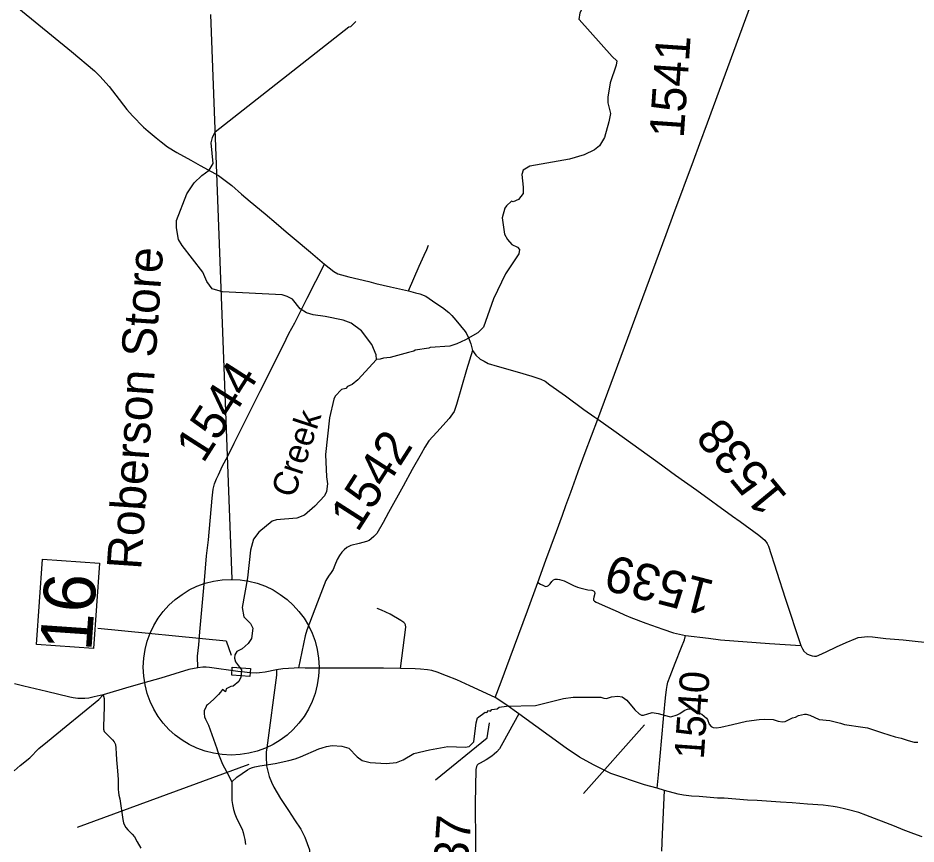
# Model space of a CAD drawing. Extents: x 2599057 to 2600057, y 728628 to 732947.
# Drawn here: x 2599143.3 to 2599259.1, y 731800 to 731906.7 of the extents above; entities that cross this region are included whole.
import ezdxf

# ---------------------------------------------------------------- set-up
doc = ezdxf.new("R2010")
doc.units = 0
for name, color, linetype in [('Old_Level_1', 7, 'Continuous'), ('Old_Level_29', 7, 'Continuous'), ('Old_Level_31', 7, 'Continuous'), ('Old_Level_32', 7, 'Continuous'), ('Old_Level_38', 7, 'Continuous'), ('Old_Level_50', 7, 'Continuous'), ('Old_Level_59', 7, 'Continuous')]:
    doc.layers.add(name, color=color, linetype=linetype)

msp = doc.modelspace()

# ---------------------------------------------------------------- linework, layer by layer
at = {"layer": 'Old_Level_1'}
msp.add_line((2599170.91, 731834.22), (2599168.16, 731907.13), dxfattribs=at)
msp.add_circle((2599170.77, 731822.87), 11.34, dxfattribs=at)
at = {"layer": 'Old_Level_29'}
msp.add_line((2599226.69, 731806.97), (2599225.71, 731807.27), dxfattribs=at)
for points in [[(2599166.45, 731822.8), (2599165.29, 731822.56), (2599161.7, 731821.47), (2599160.14, 731821.03), (2599157.58, 731820.28), (2599154.24, 731819.31)], [(2599172.1, 731822.26), (2599171.61, 731822.31), (2599167.99, 731822.85), (2599167.53, 731822.88), (2599167.11, 731822.86), (2599166.45, 731822.8)], [(2599176.63, 731822.53), (2599175.14, 731822.24), (2599174.44, 731822.14), (2599174.06, 731822.1), (2599173.22, 731822.13), (2599172.1, 731822.26)], [(2599179.44, 731822.78), (2599178.89, 731822.74), (2599177.45, 731822.65), (2599176.63, 731822.53)], [(2599192.63, 731822.7), (2599190.42, 731822.75), (2599183.31, 731822.75), (2599180.31, 731822.76), (2599179.44, 731822.78)], [(2599204.83, 731818.96), (2599201.57, 731820.46), (2599199.86, 731821.23), (2599198.54, 731821.78), (2599197.33, 731822.25), (2599196.67, 731822.44), (2599196.11, 731822.54), (2599195.2, 731822.63), (2599194.52, 731822.66), (2599192.63, 731822.7)], [(2599154.24, 731819.31), (2599153.1, 731819.05), (2599152.4, 731818.88), (2599151.89, 731818.83), (2599151.57, 731818.84), (2599150.99, 731818.84), (2599150.38, 731818.91), (2599149.94, 731818.99), (2599146.94, 731819.75), (2599144.04, 731820.42), (2599142.84, 731820.74)], [(2599207.89, 731816.84), (2599206.2, 731818.04), (2599204.83, 731818.96)], [(2599225.71, 731807.27), (2599224.08, 731807.69), (2599219.76, 731809.16), (2599218.98, 731809.53), (2599218.36, 731809.83), (2599217.5, 731810.27), (2599215.7, 731811.28), (2599213.99, 731812.43), (2599207.89, 731816.84)], [(2599259.9, 731800.97), (2599258.83, 731801.37), (2599257.45, 731801.88), (2599256.32, 731802.36), (2599252.64, 731803.79), (2599251.73, 731804.11), (2599250.22, 731804.51), (2599249.71, 731804.63), (2599248.93, 731804.8), (2599248.41, 731804.88), (2599247.13, 731805.07), (2599245.11, 731805.21), (2599243.13, 731805.36), (2599241.62, 731805.46), (2599238.63, 731805.68), (2599237.37, 731805.73), (2599234.38, 731805.96), (2599233.49, 731805.99), (2599231.15, 731806.2), (2599230.17, 731806.25), (2599229.14, 731806.36), (2599228.44, 731806.48), (2599226.69, 731806.97)]]:
    msp.add_lwpolyline(points, dxfattribs=at)
at = {"layer": 'Old_Level_31'}
for p, q in [((2599201.09, 731866.03), (2599201.09, 731866.03)), ((2599172.05, 731822.25), (2599172.05, 731822.25)), ((2599205.61, 731818.47), (2599205.61, 731818.47)), ((2599226.49, 731816.7), (2599226.49, 731816.7)), ((2599216.21, 731806.58), (2599224.09, 731815.45)), ((2599150.95, 731802.23), (2599173.1, 731810.35)), ((2599175.34, 731810.11), (2599175.34, 731810.11))]:
    msp.add_line(p, q, dxfattribs=at)
for points in [[(2599153.79, 731836.3), (2599153.03, 731825.31), (2599145.68, 731825.82), (2599146.44, 731836.81), (2599153.79, 731836.3)], [(2599153.58, 731827.92), (2599170.11, 731826.29), (2599170.77, 731824.44)], [(2599197.11, 731808.35), (2599203.79, 731813.77), (2599204.11, 731815.7)]]:
    msp.add_lwpolyline(points, dxfattribs=at)
at = {"layer": 'Old_Level_32'}
for points in [[(2599218.06, 731854.89), (2599221.94, 731865.36), (2599223.46, 731869.43), (2599224.29, 731871.74), (2599226.88, 731878.72), (2599227.87, 731881.42), (2599230.41, 731888.22), (2599231.23, 731890.45), (2599232.2, 731893.12), (2599237.18, 731906.61), (2599244.57, 731926.73), (2599247.08, 731933.51), (2599249.88, 731941.02), (2599250.89, 731943.93)], [(2599143.4, 731907.91), (2599150.19, 731902.36), (2599153.15, 731899.87), (2599153.84, 731899.17), (2599155.02, 731897.81), (2599155.89, 731896.69), (2599157.33, 731894.87), (2599158.06, 731894.02), (2599159.47, 731892.56), (2599160.05, 731892.07), (2599161.09, 731891.18), (2599161.73, 731890.68), (2599162.54, 731890.04), (2599163.75, 731889.31), (2599165.58, 731888.31), (2599166.77, 731887.63), (2599167.79, 731887.07), (2599169.12, 731886.33), (2599170.84, 731885.05), (2599172.12, 731883.95), (2599173.23, 731883), (2599175.16, 731881.39), (2599176.56, 731880.19), (2599177.86, 731879.05), (2599178.89, 731878.19), (2599180.99, 731876.44), (2599182.83, 731874.89)], [(2599193.63, 731871.44), (2599195.02, 731874.62), (2599195.68, 731876.06), (2599196, 731876.78), (2599196.24, 731877.35)], [(2599166.45, 731822.8), (2599166.42, 731824.3), (2599166.58, 731825.78), (2599166.72, 731827.46), (2599167.35, 731834.08), (2599167.6, 731837.25), (2599167.85, 731839.33), (2599168.32, 731844.69), (2599168.46, 731845.85), (2599168.61, 731846.53), (2599168.89, 731847.17), (2599169.12, 731847.69), (2599169.67, 731848.86), (2599170.35, 731850.13), (2599171.15, 731851.78), (2599174.51, 731858.5), (2599177.51, 731864.47), (2599178.21, 731865.93), (2599178.97, 731867.33), (2599180.57, 731870.52), (2599182.83, 731874.89)], [(2599182.83, 731874.89), (2599184.02, 731873.95), (2599184.52, 731873.66), (2599185.97, 731873.26), (2599188.55, 731872.64), (2599189.44, 731872.4), (2599191.34, 731871.98), (2599193.63, 731871.44)], [(2599193.63, 731871.44), (2599194.53, 731871.2), (2599195.1, 731871.05), (2599195.9, 731870.77), (2599197.17, 731869.86), (2599198.02, 731869.3), (2599198.83, 731868.66), (2599199.24, 731868.28), (2599199.75, 731867.65), (2599200.96, 731866.22), (2599201.05, 731866.06)], [(2599201.05, 731866.06), (2599201.34, 731865.53), (2599201.68, 731864.6), (2599201.91, 731863.74)], [(2599201.91, 731863.74), (2599201.14, 731861.24), (2599199.82, 731856.8), (2599199.52, 731855.87), (2599198.89, 731854.98), (2599197.29, 731853.23), (2599196.27, 731852.08), (2599195.75, 731851.28), (2599195.29, 731850.42), (2599194.13, 731848.39), (2599192.96, 731846.26), (2599191.08, 731842.86), (2599190.37, 731841.57), (2599189.56, 731840.14), (2599189.19, 731839.73), (2599188.85, 731839.43), (2599188.56, 731839.24), (2599188.24, 731839.08), (2599187.28, 731838.83), (2599186.21, 731838.57), (2599185.7, 731838.31), (2599185.34, 731838.02), (2599185.05, 731837.74), (2599184.73, 731837.31), (2599184.44, 731836.76), (2599184.14, 731836.04), (2599183.91, 731835.49), (2599183.66, 731835.08), (2599183.33, 731834.64), (2599182.97, 731834.07), (2599181.89, 731831.26), (2599180.52, 731827.67), (2599180.33, 731826.94), (2599179.44, 731822.78)], [(2599201.91, 731863.74), (2599202.33, 731863.17), (2599202.9, 731862.65), (2599203.39, 731862.36), (2599203.91, 731862.09), (2599205.1, 731861.71), (2599207.66, 731860.98), (2599209.57, 731860.45), (2599210.72, 731860.05), (2599211.26, 731859.8), (2599211.88, 731859.33), (2599213.89, 731857.88), (2599216.28, 731856.12), (2599217.67, 731855.14), (2599218.06, 731854.89)], [(2599210.35, 731833.79), (2599211.38, 731836.71), (2599212.03, 731838.52), (2599212.73, 731840.41), (2599213.5, 731842.49), (2599213.93, 731843.73), (2599214.57, 731845.47), (2599215.24, 731847.29), (2599215.53, 731848.13), (2599216.44, 731850.57), (2599218.06, 731854.89)], [(2599218.06, 731854.89), (2599220.13, 731853.44), (2599225.82, 731849.34), (2599228.09, 731847.66), (2599230.84, 731845.71), (2599235.42, 731842.35), (2599236.41, 731841.67), (2599238.84, 731839.92), (2599239.62, 731839.28), (2599239.92, 731838.86), (2599240.07, 731838.5), (2599242.24, 731831.77), (2599244.26, 731825.67)], [(2599204.83, 731818.96), (2599205.62, 731820.97), (2599206.77, 731824.14), (2599208.98, 731830.14), (2599210.35, 731833.79)], [(2599210.35, 731833.79), (2599210.69, 731833.6), (2599210.97, 731833.46), (2599211.31, 731833.31), (2599211.55, 731833.33), (2599211.7, 731833.4), (2599211.94, 731833.65), (2599212.14, 731833.95), (2599212.33, 731834.14), (2599212.57, 731834.24), (2599212.87, 731834.25), (2599213.14, 731834.2), (2599213.73, 731834.03), (2599214.94, 731833.42), (2599215.44, 731833.22), (2599215.74, 731833.13), (2599216.8, 731832.87), (2599217.29, 731832.8), (2599217.51, 731832.72), (2599217.65, 731832.62), (2599217.68, 731832.4), (2599217.54, 731831.93), (2599217.49, 731831.7), (2599217.51, 731831.53), (2599217.63, 731831.39), (2599217.86, 731831.27), (2599219.33, 731830.64), (2599220.69, 731830.02), (2599221.5, 731829.64), (2599222.34, 731829.3), (2599224.28, 731828.58), (2599226.46, 731827.8), (2599227.85, 731827.31), (2599228.59, 731827.12), (2599229.38, 731826.95)], [(2599192.63, 731822.7), (2599193.3, 731828.03), (2599193.28, 731828.35), (2599193.17, 731828.52), (2599193.03, 731828.65), (2599192.64, 731828.92), (2599191.27, 731829.7), (2599190.15, 731830.25), (2599189.59, 731830.46)], [(2599226.6, 731816.7), (2599226.8, 731818.9), (2599226.92, 731819.98), (2599227.01, 731820.5), (2599227.1, 731820.94), (2599227.38, 731821.73), (2599228.05, 731823.41), (2599228.88, 731825.48), (2599229.23, 731826.39), (2599229.38, 731826.95)], [(2599229.38, 731826.95), (2599232.36, 731826.61), (2599233.9, 731826.42), (2599240.22, 731825.95), (2599244.26, 731825.67)], [(2599244.26, 731825.67), (2599244.46, 731825.25), (2599244.63, 731824.96), (2599245.05, 731824.62), (2599245.31, 731824.48), (2599245.71, 731824.35), (2599246.02, 731824.31), (2599246.28, 731824.32), (2599246.57, 731824.42), (2599247.53, 731824.87), (2599248.86, 731825.5), (2599250.09, 731826.05), (2599251.34, 731826.6), (2599251.67, 731826.71), (2599252.91, 731826.84), (2599253.49, 731826.79), (2599255.2, 731826.59), (2599257.44, 731826.39), (2599261.75, 731825.95)], [(2599176.63, 731822.53), (2599176.61, 731821.85), (2599175.38, 731812.47), (2599175.3, 731811.91), (2599175.3, 731811.33), (2599175.33, 731810.13), (2599175.54, 731809.29), (2599175.66, 731808.77), (2599175.96, 731808.03), (2599176.28, 731807.39), (2599177.14, 731805.93), (2599178.18, 731804.4), (2599178.94, 731803.19), (2599179.74, 731801.97), (2599180.26, 731800.95), (2599180.87, 731799.32), (2599181.23, 731794.4), (2599181.37, 731791.19), (2599181.53, 731788.46), (2599181.57, 731787.42), (2599181.6, 731786.03), (2599181.57, 731785.36), (2599181.23, 731783.39), (2599181.07, 731782.53)], [(2599142.77, 731809.52), (2599143.56, 731810.18), (2599144.79, 731811.18), (2599145.98, 731812.39), (2599147.09, 731813.3), (2599149.5, 731815.27), (2599153.68, 731818.69), (2599154.24, 731819.31)], [(2599154.24, 731819.31), (2599154.38, 731818.85), (2599154.41, 731818.53), (2599154.41, 731817.82), (2599154.3, 731815.17), (2599154.32, 731814.86), (2599154.4, 731814.59), (2599154.59, 731814.36), (2599155.01, 731813.96), (2599155.46, 731813.51), (2599155.7, 731813.23), (2599155.84, 731812.91), (2599155.9, 731812.44), (2599155.95, 731811.75), (2599156, 731810.91), (2599156.09, 731809.52), (2599156.19, 731808.36), (2599156.18, 731807.62), (2599156.19, 731807.08), (2599156.24, 731806.74), (2599156.3, 731806.36), (2599156.41, 731805.88), (2599156.8, 731803.21), (2599156.89, 731802.78), (2599157, 731802.48), (2599157.17, 731802.2), (2599157.43, 731801.9), (2599158.02, 731801.32), (2599158.3, 731800.97), (2599158.65, 731800.33), (2599159.11, 731799.51)], [(2599207.89, 731816.84), (2599205.83, 731813.13), (2599205.38, 731812.36), (2599205.06, 731811.96), (2599204.71, 731811.64), (2599204.4, 731811.39), (2599203.68, 731810.94), (2599202.87, 731810.5), (2599202.65, 731810.38), (2599202.5, 731810.23), (2599202.4, 731810.04), (2599202.35, 731809.69), (2599202.3, 731807.49), (2599202.26, 731805.28), (2599202.27, 731800.12), (2599202.39, 731795.32)], [(2599225.71, 731807.27), (2599225.89, 731809), (2599226.56, 731816.23), (2599226.6, 731816.7)], [(2599226.32, 731799.13), (2599226.43, 731801.31), (2599226.69, 731806.97)]]:
    msp.add_lwpolyline(points, dxfattribs=at)
at = {"layer": 'Old_Level_38'}
msp.add_lwpolyline([(2599170.85, 731821.84), (2599170.92, 731822.86), (2599173.25, 731822.7), (2599173.18, 731821.68)], close=True, dxfattribs=at)
at = {"layer": 'Old_Level_50'}
for p, q in [((2599201.07, 731866.08), (2599201.07, 731866.08)), ((2599172.08, 731822.27), (2599172.08, 731822.27)), ((2599205.51, 731818.46), (2599205.51, 731818.46)), ((2599226.59, 731816.73), (2599226.59, 731816.73)), ((2599175.4, 731810.2), (2599175.4, 731810.2))]:
    msp.add_line(p, q, dxfattribs=at)
at = {"layer": 'Old_Level_59'}
for points in [[(2599220.5, 731901.12), (2599219.93, 731901.71), (2599215.68, 731906.49), (2599215.77, 731907.32), (2599224.99, 731926.97), (2599225.02, 731928.7), (2599224.83, 731929.22), (2599223.88, 731930.21), (2599217.55, 731935.09), (2599216.24, 731935.15), (2599209.54, 731932.89), (2599209.3, 731933.18), (2599208.81, 731955.47)], [(2599189.52, 731862.58), (2599189.49, 731863.2), (2599188.91, 731864.51), (2599187.57, 731866.31), (2599186.24, 731867.27), (2599185.21, 731867.65), (2599182.89, 731868.15), (2599181.37, 731868.34), (2599180.48, 731868.6), (2599179.67, 731869.14), (2599178.7, 731870.36), (2599177.98, 731870.73), (2599177.37, 731870.92), (2599169.64, 731871.34), (2599168.34, 731871.69), (2599167.64, 731872.67), (2599167.11, 731873.87), (2599164.43, 731877.29), (2599163.99, 731878.09), (2599163.7, 731879.57), (2599163.73, 731880.51), (2599165.07, 731883.97), (2599165.98, 731885.38), (2599166.99, 731886.34), (2599167.93, 731887.02), (2599168.44, 731887.89), (2599168.2, 731890.54), (2599168.35, 731891.25), (2599168.71, 731891.97), (2599185.94, 731905.53), (2599186.21, 731905.57), (2599186.84, 731906.22)], [(2599220.5, 731901.12), (2599220.42, 731900.56), (2599219.66, 731898.31), (2599219.36, 731896.47), (2599219.37, 731895.74)], [(2599219.37, 731895.74), (2599219.69, 731894.33), (2599219.47, 731893.28), (2599218.95, 731891.24), (2599218.27, 731890.15), (2599217.65, 731889.67), (2599216.29, 731889.02), (2599214.42, 731888.43), (2599209.29, 731887.55), (2599208.42, 731887.03), (2599208.27, 731886.48), (2599208.45, 731884.85), (2599208.43, 731884.01), (2599207.84, 731883.26), (2599207.15, 731882.95), (2599206.94, 731883.02), (2599206.28, 731882.43), (2599206.06, 731882.11), (2599205.73, 731880.89), (2599206.04, 731878.75), (2599206.43, 731878.07), (2599206.98, 731877.43), (2599207.72, 731877.11), (2599207.96, 731876.77), (2599207.88, 731876.21), (2599206.15, 731873.66), (2599204.62, 731870.43), (2599203.34, 731866.75), (2599202.61, 731866.05), (2599200.98, 731865.12), (2599199.9, 731864.61), (2599198.97, 731864.32), (2599196.42, 731864.16), (2599196.25, 731864.06), (2599194.49, 731863.8), (2599194.32, 731863.65), (2599193.63, 731863.51), (2599191.27, 731862.84), (2599190.42, 731862.77), (2599190, 731862.62), (2599189.52, 731862.58)], [(2599189.52, 731862.58), (2599187.1, 731859.96), (2599186.4, 731859.38), (2599185.78, 731859.12), (2599185.57, 731858.85), (2599185.02, 731858.71), (2599184.2, 731857.85), (2599184.02, 731857.48), (2599183.47, 731855.04), (2599182.93, 731850.31), (2599183.05, 731847.45), (2599183.21, 731846.55), (2599183.06, 731845.55), (2599182.81, 731845), (2599181.58, 731843.66), (2599180.21, 731842.5), (2599179.24, 731842.09), (2599176.63, 731841.88), (2599176.04, 731841.74), (2599174.33, 731840.31), (2599173.64, 731839.4), (2599173.26, 731837.96), (2599172.86, 731834.39), (2599172.2, 731830.57), (2599172.41, 731829.39), (2599173.26, 731828.51), (2599173.56, 731827.93), (2599173.39, 731826.6), (2599172.98, 731825.95), (2599172.21, 731825.26), (2599171.51, 731824.9), (2599171.26, 731824.46), (2599171.19, 731824.02), (2599171.32, 731823.56), (2599172.12, 731822.52), (2599172.03, 731821.57), (2599171.74, 731821.03), (2599171.02, 731820.44), (2599170.74, 731820.4), (2599170.11, 731820.1), (2599170.04, 731819.71), (2599169.66, 731819.99), (2599169.41, 731819.66), (2599169.13, 731819.34), (2599168.82, 731819.04), (2599168.54, 731818.77), (2599167.71, 731818.01), (2599167.59, 731817.93), (2599167.53, 731817.79), (2599167.3, 731817.23), (2599167.27, 731816.9), (2599167.34, 731816.48), (2599167.47, 731816.18), (2599167.85, 731815.38), (2599168.94, 731812.39), (2599169.12, 731811.65), (2599169.39, 731810.99), (2599169.65, 731810.35), (2599170.15, 731809.4), (2599170.86, 731808.07)], [(2599170.86, 731808.07), (2599171.52, 731808.67), (2599172.88, 731809.63), (2599173.17, 731809.79), (2599173.51, 731809.93), (2599173.84, 731810.02), (2599174.46, 731810.15), (2599176.45, 731810.43), (2599178.21, 731810.82), (2599179.01, 731811.06), (2599179.71, 731811.32), (2599182.07, 731812.33), (2599182.49, 731812.47), (2599183.09, 731812.64), (2599183.82, 731812.76), (2599185.04, 731812.69), (2599185.93, 731812.42), (2599187.04, 731811.31), (2599187.65, 731810.83), (2599188.71, 731810.56), (2599190.77, 731810.46), (2599192.11, 731810.57), (2599192.97, 731810.91), (2599194.33, 731811.75), (2599196.37, 731812.21), (2599198.72, 731812.66), (2599200.94, 731812.56), (2599201.47, 731812.64), (2599202.09, 731813.23), (2599202.37, 731815.68), (2599202.56, 731816.34), (2599203.54, 731817.07), (2599203.75, 731817.02), (2599203.98, 731817.28), (2599204.23, 731817.22), (2599204.4, 731817.43), (2599205.1, 731817.51), (2599205.33, 731817.72), (2599206.29, 731817.85), (2599210.05, 731817.95), (2599213.64, 731818.84), (2599214.88, 731819.01), (2599218.45, 731818.99)], [(2599218.45, 731818.99), (2599218.83, 731818.89), (2599219.17, 731818.85), (2599219.83, 731819.05), (2599220.65, 731819.12), (2599221.2, 731819.04), (2599221.8, 731818.61), (2599222.83, 731817.38), (2599223.4, 731816.84), (2599223.71, 731816.69), (2599223.96, 731816.68), (2599224.52, 731816.86), (2599224.93, 731817), (2599225.06, 731817.01)], [(2599225.06, 731817.01), (2599225.85, 731816.89), (2599226.32, 731816.79), (2599227.27, 731816.5), (2599227.5, 731816.48), (2599228.32, 731816.71), (2599228.64, 731816.88), (2599229.2, 731817.28), (2599229.72, 731817.51), (2599230.17, 731817.45), (2599230.8, 731817.15), (2599230.93, 731817.03), (2599231.5, 731816.8), (2599232.09, 731816.29), (2599232.2, 731816.13), (2599232.41, 731815.52), (2599232.68, 731815.2), (2599232.95, 731815.11), (2599233.37, 731815.05), (2599233.93, 731815.13), (2599235.45, 731815.47), (2599237.25, 731815.93), (2599238.89, 731816.13), (2599239.55, 731816.18), (2599240.68, 731816.14), (2599241.34, 731815.91), (2599241.91, 731815.81), (2599242.23, 731815.87), (2599243.17, 731816.32), (2599243.55, 731816.41), (2599243.96, 731816.62), (2599244.75, 731816.8), (2599244.95, 731816.8), (2599245.41, 731816.68), (2599246.63, 731816.14), (2599248.01, 731815.99), (2599249.37, 731815.64), (2599249.87, 731815.47), (2599252.27, 731815.13), (2599252.85, 731815.06), (2599254.79, 731814.41), (2599256.42, 731813.9), (2599257.22, 731813.72), (2599258.1, 731813.41), (2599258.89, 731813.22), (2599259.37, 731813.18)], [(2599170.86, 731808.07), (2599170.87, 731805.68), (2599170.96, 731805.16), (2599171.06, 731804.52), (2599171.23, 731803.95), (2599171.51, 731803.29), (2599172.18, 731801.96), (2599172.32, 731801.54), (2599172.41, 731801.17), (2599172.52, 731800.63), (2599172.63, 731800)]]:
    msp.add_lwpolyline(points, dxfattribs=at)

# ---------------------------------------------------------------- texts
at = {"layer": 'Old_Level_1'}
for s, height, rotation, p in [('1541', 4.446, 86.0601, (2599229.14, 731891.1)), ('Roberson Store', 4.4457, 86.0601, (2599159.15, 731835.4)), ('1544', 4.509, 57.3831, (2599167.17, 731849.08)), ('Creek', 3.188, 71.8166, (2599178.89, 731844.6)), ('1538', 4.571, 129.5119, (2599242.67, 731844.89)), ('1542', 4.509, 57.3831, (2599187.09, 731840.17)), ('1539', 4.685, 165.5167, (2599233.32, 731833.96)), ('1540', 3.811, 86.0601, (2599231.73, 731810.93)), ('1537', 4.446, 86.0601, (2599200.85, 731790.42))]:
    msp.add_text(s, height=height, rotation=rotation, dxfattribs=at).set_placement(p)
at = {"layer": 'Old_Level_31'}
msp.add_text('16', height=6.668, rotation=86.0601, dxfattribs=at).set_placement((2599152.73, 731824.83))

doc.saveas('drawing.dxf')
